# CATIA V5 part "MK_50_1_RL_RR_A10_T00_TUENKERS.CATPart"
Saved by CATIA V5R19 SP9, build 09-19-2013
Part number: MK_50_1_RL_RR_A10_T00_TUENKERS
Material "MISCHDICHTE": density 4834.5 kg/m3, Young's modulus 2e+11 Pa, Poisson ratio 0.266
Bounding box of the stored display mesh (mm): x -173.5 to 150.266, y -96.5 to 144, z -119.161 to 119.161
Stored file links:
  G:\Konstruktion\Modelle\Catia_V5\MK_50_1_RL_RR_A10_T00_TUENKERS.CATPart
  G:\Konstruktion\Modelle\Catia_V5\Spannarme\SPANNARM_KPL_50_A10_216884_TUENKERS.CATPart
  C:\Catia\Tuenkers_B19SP9HF86_64\win_b64\reffiles\standard\MetricThickPitch.txt
  G:\Konstruktion\Modelle\Catia_V5\MK2_50_1_A40_T00_TUENKERS.CATPart
  G:\Konstruktion\Modelle\Catia_V5\V2_50_1_BR3_ZL_ZR_RL_RR_A40_T12_TUENKERS.CATPart
  HANDHEBEL_KPL_50_63_TUENKERS.CATPart
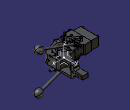
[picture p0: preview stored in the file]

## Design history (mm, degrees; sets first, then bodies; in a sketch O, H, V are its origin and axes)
AxisSystem1: origin (0, 0, 0), X (1, 0, 0), Y (0, 1, 0), Z (0, 0, 1)
Body1 (main body)
  Body2 "*DIT1\\*DIT8\\PartBody ( *SOL6 - wsp HANDHEBEL -  )"
    Solid1 "Solid.1": solid without history
  Assemble1: tool Body2
  Body3 "*DIT1\\*DIT9\\Body.9 ( *SOL4 - wsp T 12 ABFRAGE -  )"
    Sketch1 on face of Solid6, origin (0, 0, 88.5), H (1, 0, 0), V (0, 1, 0)
      line L1 (-98, 23.5) -> (-93.5, 23.5)
      line L2 (-93.5, 23.5) -> (-93.5, -23.5)
      line L3 (-93.5, -23.5) -> (-98, -23.5)
      line L4 (-98, -23.5) -> (-98, 23.5)
      line L5 (-126.5, 11.5) -> (-116.2, 11.5)
      line L6 (-116.2, 11.5) -> (-116.2, -5.5)
      line L7 (-116.2, -5.5) -> (-126.5, -5.5)
      line L8 (-126.5, -5.5) -> (-126.5, 11.5)
      reference projected line E1 (-126.5, -23.5) -> (-93.5, -23.5) from edge [face of Solid6 | face of Solid6]
      reference projected line E2 (-126.5, 23.5) -> (-93.5, 23.5) from edge [face of Solid6 | face of Solid6]
      reference projected line E3 (-93.5, 23.5) -> (-93.5, -23.5) from edge [face of Solid6 | face of Solid6]
      reference projected line E4 (-126.5, 23.5) -> (-93.5, 23.5) from edge [face of Solid6 | face of Solid6]
      reference projected line E5 (-126.5, 23.5) -> (-126.5, -23.5) from edge [face of Solid6 | face of Solid6]
      distance E1 L3 = 0
      distance L1 E2 = 0
      distance L2 L4 = 4.5
      distance L2 E3 = 0
      length L8 = 17
      distance L5 E4 = 12
      distance L6 L4 = 18.2
      distance L8 E5 = 0
      horizontal: L1 H, L3 H, L5 H, L7 H
      vertical: L2 V, L4 V, L6 V, L8 V
    Pad1: profile Sketch1, direction (0, 0, 1), length 8
    Chamfer1: length 4, angle 30, on edge [face of Pad1 from Sketch1.L2 | end face of Pad1]
    Chamfer2: length 8, angle 45, on edge [face of Pad1 from Sketch1.L8 | end face of Pad1]
  Assemble2: tool Body3
  Body4 "*DIT1\\*DIT10\\*DIT17\\PartBody ( *SOL17 - wsp DREHBOLZEN -  )"
    Solid2 "Solid.1": solid without history
  Assemble3: tool Body4
  Body5 "*DIT1\\*DIT10\\*DIT18\\PartBody ( *SOL18 - wsp STOESSEL -  )"
    Solid3 "Solid.1": solid without history
  Assemble4: tool Body5
  Body6 "*DIT1\\*DIT10\\MK_MK2_50_1_A10_A11_A12_T12_081112_3D_xSET3_1.1\\PartBody ( *SOL13 - wsp GEHAEUSE -  )"
    Solid4 "Solid.1": solid without history
  Assemble5: tool Body6
  Body7 "*DIT1\\MK_MK2_50_1_A10_A11_A12_T12_081112_3D_xSET2.1\\PartBody ( *SOL1 - wsp MK_MK2 50_1 -  -Non Smart-  )"
    Solid5 "Solid.1": solid without history
  Assemble6: tool Body7
  Body8 "*DIT1\\MK_MK2_50_1_A10_A11_A12_T12_081112_3D_xSET2.1\\Body.2 ( *SOL2 - wsp MK_MK2 50_1 -  -Non Smart-  )"
    Solid6 "Solid.1": solid without history
  Assemble7: tool Body8
  Body9 "*DIT1\\MK_MK2_50_1_A10_A11_A12_T12_081112_3D_xSET2.1\\Body.3 ( *SOL24 - wsp MK_MK2 50_1 -  )"
    Solid7 "Solid.1": solid without history
  Assemble8: tool Body9
  Body10 "*DIT1\\MK_MK2_50_1_A10_A11_A12_T12_081112_3D_xSET2.1\\Body.4 ( *SOL25 - wsp MK_MK2 50_1 -  )"
    Solid8 "Solid.1": solid without history
  Assemble9: tool Body10
  Body11 "*DIT1\\MK_MK2_50_1_A10_A11_A12_T12_081112_3D_xSET2.1\\Body.5 ( *SOL26 - wsp MK_MK2 50_1 -  )"
    Solid9 "Solid.1": solid without history
  Assemble10: tool Body11
  Body12 "*DIT1\\MK_MK2_50_1_A10_A11_A12_T12_081112_3D_xSET2.1\\Body.6 ( *SOL27 - wsp MK_MK2 50_1 -  )"
    Solid10 "Solid.1": solid without history
  Assemble11: tool Body12
  Body13 "*DIT1\\MK_MK2_50_1_A10_A11_A12_T12_081112_3D_xSET2.1\\Body.7 ( *SOL28 - wsp MK_MK2 50_1 -  )"
    Solid11 "Solid.1": solid without history
  Assemble12: tool Body13
  Rotate1: Axis edge [XY plane of AxisSystem1 | ZX plane of AxisSystem1], Angle 90, ToTransfor Assemble12
Body14 "Spannarm_kpl_50_A10_216884_Tuenkers", material "Steel"
  Sketch2 on xy-plane, origin (0, 0, 0), H (1, 0, 0), V (0, 1, 0)
    line L1 (43, 144) -> (15, 144)
    line L2 (35.6421, 1.701) -> (16.9706, -16.9706)
    line L3 (9.5, 9.5) -> (9.5, -9.5)
    line L4 (9.5, 9.5) -> (-9.5, 9.5)
    line L5 (-16.9706, 16.9706) -> (-9.5, 9.5)
    line L6 (10.6421, 44.5833) -> (-16.9706, 16.9706)
    line L7 (16.5, 58.7254) -> (16.5, 78.5)
    line L8 (43, 144) -> (43, 80)
    line L9 (9.5, -9.5) -> (16.9706, -16.9706)
    point P8 (43, 9.0589)
    point P9 (16.5, 51.7188)
    reference intersected line E1 through (0, 0) direction (-1, 0)
    reference intersected line E2 through (0, 0) direction (0, 1)
    reference intersected line E3 through (0, 0) direction (-0.7071, -0.7071)
    line L10 (41.5, 78.5) -> (41.5, 15.8431)
    reference intersected line E4 through (0, 0) direction (0, 1) from yz-plane
    line L11 (15, 80) -> (15, 144)
    point P10 (15, 80)
    reference intersected line E5 through (0, 0) direction (0, 1) from yz-plane
    arc A1 centre (43, 78.5) radius 1.5 from (41.5, 78.5) to (43, 80) cw
    arc A2 centre (15, 78.5) radius 1.5 from (16.5, 78.5) to (15, 80) ccw
    arc A3 centre (21.5, 15.8431) radius 20 from (35.6421, 1.701) to (41.5, 15.8431) ccw
    arc A4 centre (-3.5, 58.7254) radius 20 from (10.6421, 44.5833) to (16.5, 58.7254) ccw
    length L3 = 19
    length L4 = 19
    angle L5 L4 = 45
    angle L3 L9 = 45
    distance L2 L6 = 48
    distance L4 L1 = 134.5
    distance P9 L4 = 42.2188
    distance L4 E1 = 9.5
    distance L3 E2 = 9.5
    distance L2 E3 = 24
    distance L10 E4 = 41.5
    distance E5 L11 = 15
    distance L7 L10 = 25
    distance L8 L11 = 28
    length L8 = 64
    radius A3 = 20
    radius A4 = 20
    radius A1 = 1.5
    radius A2 = 1.5
    length L11 = 64
    vertical: L3 V
    horizontal: L4 H
    tangency: A3 L10, L2 A3, L7 A2, L10 A1, L7 A4, L6 A4
  Pad2: profile Sketch2, direction (0, 0, 1), length 34, mirrored extent
  Chamfer3: length 0.1, angle 45, on edge [start face of Pad2 | face of Pad2 from Sketch2.L3]; edge [start face of Pad2 | face of Pad2 from Sketch2.L4]; edge [face of Pad2 from Sketch2.L4 | end face of Pad2]; edge [face of Pad2 from Sketch2.L3 | end face of Pad2]
  Sketch3 on face of Pad2 from Sketch2.L8, origin (43, 0, 0), H (0, 1, 0), V (0, 0, 1)
    line L1 (144, -10) -> (144, 10)
    line L2 (103, 10) -> (144, 10)
    arc A1 centre (103, 18) radius 8 from (103, 10) to (95, 18) cw
    line L3 (95, 18) -> (95, 21.0383)
    line L4 (-18, 34) -> (75, 34)
    line L5 (-18, 34) -> (-18, 25)
    line L6 (74, 25) -> (-18, 25)
    arc A2 centre (74, 19) radius 6 from (74, 25) to (80, 19) cw
    line L7 (80, 19) -> (80, -19)
    arc A3 centre (74, -19) radius 6 from (80, -19) to (74, -25) cw
    line L8 (-18, -25) -> (74, -25)
    line L9 (-18, -25) -> (-18, -34)
    line L10 (75, -34) -> (-18, -34)
    line L11 (95, -21.0383) -> (95, -18)
    arc A4 centre (103, -18) radius 8 from (95, -18) to (103, -10) cw
    line L12 (103, -10) -> (144, -10)
    reference intersected line E1 through (0, 0) direction (-1, 0) from xy-plane
    reference intersected line E2 through (0, 0) direction (0, 1) from zx-plane
    reference intersected line E3 through (0, 0) direction (0, 1) from zx-plane
    reference intersected line E4 through (0, 0) direction (0, 1) from zx-plane
    line L13 (-23, -39) -> (149, -39)
    line L14 (149, -39) -> (149, 39)
    line L15 (149, 39) -> (-23, 39)
    line L16 (-23, 39) -> (-23, -39)
    reference intersected line E5 through (0, 0) direction (-1, 0) from xy-plane
    reference intersected line E6 through (0, 0) direction (0, 1) from zx-plane
    line L17 (75.5176, -33.9319) -> (87.5882, -30.6976)
    point P18 (95, -24)
    arc A5 centre (85, -21.0383) radius 10 from (95, -21.0383) to (87.5882, -30.6976) cw
    arc A6 centre (75, -32) radius 2 from (75, -34) to (75.5176, -33.9319) ccw
    point P23 (75, -34)
    line L18 (87.5882, 30.6976) -> (75.5176, 33.9319)
    arc A7 centre (75, 32) radius 2 from (75, 34) to (75.5176, 33.9319) cw
    point P26 (75, 34)
    arc A8 centre (85, 21.0383) radius 10 from (87.5882, 30.6976) to (95, 21.0383) cw
    distance L12 E1 = 10
    distance L12 L2 = 20
    distance L4 L10 = 68
    distance L6 L8 = 50
    distance L10 L12 = 24
    distance L8 L10 = 9
    radius A2 = 6
    radius A3 = 6
    radius A1 = 8
    radius A4 = 8
    distance L7 E2 = 80
    distance L3 E3 = 95
    distance L1 L5 = 162
    distance E4 L1 = 144
    distance L16 L14 = 172
    distance L15 L13 = 78
    distance L13 E5 = 39
    distance L14 E6 = 149
    radius A5 = 10
    angle L10 L17 = 15
    radius A6 = 2
    distance L11 P23 = 20
    angle L4 L18 = 15
    distance P26 L3 = 20
    radius A8 = 10
    radius A7 = 2
    tangency: L6 A2, A2 L7, L7 A3, A3 L8, L3 A1, A1 L2, A4 L12, A4 L11, A5 L11, A5 L17, A6 L10, A6 L17, A7 L4, A7 L18, A8 L18, A8 L3
    vertical: L1 V, L14 V, L16 V
    horizontal: L12 H, L13 H, L15 H
    coincidence: L5 L9, L11 L3, L11 P18
  Pocket1: profile Sketch3, direction (-1, 0, 0), length 91
  Sketch4 on face of Pad2 from Sketch2.L8, origin (43, 131.0889, -0.3784), H (0, 1, 0), V (0, 0, 1)
    point P1 (3.9111, 0.3784)
    reference intersected line E1 through (0, 0.3784) direction (-1, 0) from xy-plane
    reference intersected line E2 through (-131.0889, 0) direction (0, 1) from zx-plane
    distance P1 E2 = 135
    coincidence: P1 E1
  Hole1: placed by Sketch4, at (43, 135, 0) direction (-1, 0, 0), diameter 6, through (limit type 6)
  Sketch5 on face of Pad2 from Sketch2.L8, origin (43, 113.9529, 0.5693), H (0, 1, 0), V (0, 0, 1)
    point P1 (-8.9529, -0.5693)
    reference projected point E1 (21.0471, -0.5693) from axis of face of Hole1
    reference intersected line E2 through (0, -0.5693) direction (-1, 0) from xy-plane
    distance P1 E1 = 30
    coincidence: P1 E2
  Hole2: placed by Sketch5, at (43, 105, 0) direction (-1, 0, 0), diameter 6, through (limit type 6)
  Sketch6 on face of Pad2 from Sketch2.L8, origin (43, 123.4122, -0.1089), H (0, 1, 0), V (0, 0, 1)
    point P1 (-3.4122, 0.1089)
    reference projected point E1 (11.5878, 0.1089) from axis of face of Hole1
    reference projected point E2 (-18.4122, 0.1089) from axis of face of Hole2
    distance P1 E1 = 15
    distance E2 P1 = 15
  Hole3: placed by Sketch6, at (43, 120, 0) direction (-1, 0, 0), diameter 9, through (limit type 6)
  Sketch7 on face of Pad2 from Sketch2.L8, origin (43, 93.5248, 1.4062), H (0, 1, 0), V (0, 0, 1)
    point P1 (-3.5248, -1.4062)
    reference projected point E1 (26.4752, -1.4062) from axis of face of Hole3
    reference projected point E2 (11.4752, -1.4062) from axis of face of Hole2
    distance P1 E1 = 30
    distance P1 E2 = 15
  Hole4: placed by Sketch7, at (43, 90, 0) direction (-1, 0, 0), diameter 9, through (limit type 6)
  Sketch8 on face of Pad2 from Sketch2.L9, origin (13.7879, -13.7879, 28.7565), H (0.7071, -0.7071, 0), V (0, 0, 1)
    point P1 (-1.4991, 0.2435)
    reference intersected line E1 through (0, -28.7565) direction (-1, 0) from xy-plane
    reference projected line E2 (-19.4991, -62.7565) -> (-19.4991, 5.2435) from edge [face of Pad2 from Sketch2.L3 | face of Pad2 from Sketch2.L4]
    distance P1 E1 = 29
    distance E2 P1 = 18
  Hole5: placed by Sketch8, at (12.7279, -12.7279, 29) direction (0.7071, 0.7071, 0), diameter 4.917, depth 16, V-bottom angle 120, threaded "M6", thread diameter 6, thread depth 14, pitch 1
  RectPattern1: of Hole5, direction 1 instances 2, spacing 58, along edge [face of Pad2 from Sketch2.L3 | face of Pad2 from Sketch2.L4] reversed, direction 2 instances 2, spacing 36, along edge [face of Pad2 from Sketch2.L9 | face of Pocket1] reversed
  Body15 "KLEMMFLANSCH KPL"
    Sketch9 on xy-plane, origin (0, 0, 0), H (1, 0, 0), V (0, 1, 0)
      line L1 (-18.3848, 15.5563) -> (-26.8771, 7.064)
      line L2 (-26.8771, 7.064) -> (-18.7454, -1.0677)
      line L3 (-18.7454, -1.0677) -> (-23.6951, -6.0175)
      line L4 (-23.6951, -6.0175) -> (-6.0175, -23.6951)
      line L5 (-6.0175, -23.6951) -> (-1.0677, -18.7454)
      line L6 (-1.0677, -18.7454) -> (7.064, -26.8771)
      line L7 (7.064, -26.8771) -> (16.9635, -16.9776)
      line L8 (16.9635, -16.9776) -> (9.3267, -9.3409)
      line L9 (9.3267, -9.3409) -> (-9.3409, -9.3409)
      point P10 (-9.3409, -9.3409)
      line L10 (-9.3409, -9.3409) -> (-9.3409, 6.5125)
      line L11 (-9.3409, 6.5125) -> (-18.3848, 15.5563)
      reference intersected line E1 through (0, 0) direction (-0.7071, -0.7071)
      reference intersected line E2 through (0, 0) direction (-0.7071, 0.7071)
      distance L4 L8 = 21
      angle L5 L6 = 90
      angle L9 L8 = 45
      distance L7 L5 = 11.5
      distance L5 L3 = 25
      distance L7 L1 = 48
      distance P10 L8 = 13.2
      distance P10 L5 = 12.5
      distance L4 L6 = 7
      angle L9 L10 = 90
      distance E2 L11 = 2
      distance L11 L8 = 1.99
      coincidence: L2 L6, E1 P10
    Pad3: profile Sketch9, direction (0, 0, 1), length 34, opposite side length -24
    Sketch10 on face of Pad3 from Sketch9.L6, origin (-9.9066, -9.9066, 0), H (0.7071, -0.7071, 0), V (0, 0, 1)
      circle A1 centre (18, 29) radius 5
      point P1 (18, 29)
      point P2 (18, 29)
      reference projected line E1 (12.5, 34) -> (24, 34) from edge [face of Pad3 from Sketch9.L6 | end face of Pad3]
      reference projected line E2 (24, 24) -> (24, 34) from edge [face of Pad3 from Sketch9.L7 | face of Pad3 from Sketch9.L6]
      radius A1 = 5
      distance E1 P2 = 5
      distance P2 E2 = 6
      coincidence: P2 P1
    Pad4: profile Sketch10, direction (-0.7071, -0.7071, 0), length 1.2
    RectPattern2: of Pad4, direction 1 instances 2, spacing 36, along edge [start face of Pad3 | face of Pad3 from Sketch9.L4] reversed
    Chamfer4: length 0.1, angle 45, on edge [face of Pad4 from Sketch10.A1 | end face of Pad4]; edge [face of RectPattern2 | face of RectPattern2]
    Sketch11 on face of Pad3 from Sketch9.L6, origin (-9.9066, -9.9066, 0), H (0.7071, -0.7071, 0), V (0, 0, 1)
      circle A1 centre (18, 29) radius 3
      point P1 (18, 29)
      reference projected line E1 (12.5, 24) -> (24, 24) from edge [start face of Pad3 | face of Pad3 from Sketch9.L6]
      reference projected line E2 (24, 24) -> (24, 34) from edge [face of Pad3 from Sketch9.L7 | face of Pad3 from Sketch9.L6]
      radius A1 = 3
      distance P1 E1 = 5
      distance E2 P1 = 6
    Pad5: profile Sketch11, direction (0.7071, 0.7071, 0), length 20
    RectPattern3: of Pad5, direction 1 instances 2, spacing 36, along edge [start face of Pad3 | face of Pad3 from Sketch9.L4] reversed
    Sketch12 on end face of Pad4, origin (-10.7551, -10.7551, 0), H (0.7071, -0.7071, 0), V (0, 0, 1)
      circle A1 centre (18, 29) radius 5
      point P1 (18, 29)
      circle A2 centre (-18, 29) radius 5
      point P2 (-18, 29)
      reference projected line E1 (-24, 24) -> (-12.5, 24) from edge [start face of Pad3 | face of Pad3 from Sketch9.L2]
      reference projected line E2 (12.5, 24) -> (24, 24) from edge [start face of Pad3 | face of Pad3 from Sketch9.L6]
      reference projected line E3 (24, 24) -> (24, 34) from edge [face of Pad3 from Sketch9.L7 | face of Pad3 from Sketch9.L6]
      reference projected line E4 (-24, 24) -> (-24, 34) from edge [face of Pad3 from Sketch9.L2 | face of Pad3 from Sketch9.L1]
      radius A1 = 5
      radius A2 = 5
      distance E1 P2 = 5
      distance E2 P1 = 5
      distance E3 P1 = 6
      distance E4 P2 = 6
    Pad6: profile Sketch12, direction (-0.7071, -0.7071, 0), length 6
    Fillet1: radius 0.5, on edge [face of Pad6 from Sketch12.A1 | end face of Pad6]; edge [face of Pad6 from Sketch12.A2 | end face of Pad6]
    Chamfer5: length 0.1, angle 45, on edge [face of Pad3 from Sketch9.L9 | end face of Pad3]; edge [face of Pad3 from Sketch9.L10 | end face of Pad3]
    Mirror1: of the body so far, about xy-plane
  Assemble13: tool Body15
  Sketch13 on face of Pocket1 from Sketch3.L6, origin (0, 0, 25), H (1, 0, 0), V (0, -1, 0)
    line L1 (16.9706, 16.9706) -> (9.5, 9.5)
    line L2 (9.5, 9.5) -> (9.5, -9.5)
    point P3 (9.5, -9.5)
    line L3 (9.5, -9.5) -> (-9.5, -9.5)
    line L4 (-9.5, -9.5) -> (-16.9706, -16.9706)
    line L5 (-16.9706, -16.9706) -> (0.7071, -34.6482)
    line L6 (0.7071, -34.6482) -> (34.6482, -0.7071)
    line L7 (34.6482, -0.7071) -> (16.9706, 16.9706)
    reference intersected line E1 through (0, 0) direction (0.7071, 0.7071)
    reference intersected line E2 through (0, 0) direction (0.7071, -0.7071)
    reference intersected line E3 through (0, 0) direction (0.7071, -0.7071)
    distance L1 L6 = 25
    angle L2 L3 = 90
    length L2 = 19
    length L3 = 19
    distance L7 L5 = 48
    distance L7 E3 = 24
    coincidence: E1 L1, L1 L4, E2 P3
  Pad7: profile Sketch13, direction (0, 0, -1), length 1
  Mirror2: of Pad7, Sketch13, about xy-plane
Body16 "ENDLAGENRASTE_LINKS"
  Body17 "LUMP108"
    Solid12 "Manifold Solid #2147": solid without history
  Assemble14: tool Body17
  Body18 "LUMP109"
    Solid13 "Manifold Solid #2556": solid without history
  Assemble15: tool Body18
  Body19 "LUMP110"
    Solid14 "Manifold Solid #2941": solid without history
  Assemble16: tool Body19
  Body20 "LUMP111"
    Solid15 "Manifold Solid #3571": solid without history
  Assemble17: tool Body20
  Body21 "LUMP112"
    Solid16 "Manifold Solid #4879": solid without history
  Assemble18: tool Body21
  Body22 "LUMP114"
    Solid17 "Manifold Solid #6444": solid without history
  Assemble19: tool Body22
  Body23 "LUMP117"
    Solid18 "Manifold Solid #8121": solid without history
  Assemble20: tool Body23
  Body24 "LUMP118"
    Solid19 "Manifold Solid #9264": solid without history
  Assemble21: tool Body24
  Body25 "LUMP120"
    Solid20 "Manifold Solid #10792": solid without history
  Assemble22: tool Body25
  Body26 "LUMP122"
    Solid21 "Manifold Solid #11586": solid without history
  Assemble23: tool Body26
  Body27 "LUMP126"
    Solid22 "Manifold Solid #12918": solid without history
  Assemble24: tool Body27
  Body28 "LUMP127"
    Solid23 "Manifold Solid #13327": solid without history
  Assemble25: tool Body28
  Body29 "LUMP130"
    Solid24 "Manifold Solid #14250": solid without history
  Assemble26: tool Body29
  Body30 "LUMP132"
    Solid25 "Manifold Solid #15068": solid without history
  Assemble27: tool Body30
  Body31 "LUMP133"
    Solid26 "Manifold Solid #15325": solid without history
  Assemble28: tool Body31
  Body32 "LUMP134"
    Solid27 "Manifold Solid #15582": solid without history
  Assemble29: tool Body32
  Body33 "LUMP135"
    Solid28 "Manifold Solid #15839": solid without history
  Assemble30: tool Body33
  Body34 "LUMP124"
    Solid29 "Manifold Solid #12404": solid without history
  Assemble31: tool Body34
  Rotate2: Axis edge, Angle 90, ToTransfor Assemble31
Body35 "ENDLAGENRASTE_RECHTS"
  Solid30 "Manifold Solid #290": solid without history
  Body36 "LUMP105"
    Solid31 "Manifold Solid #920": solid without history
  Assemble32: tool Body36
  Body37 "LUMP106"
    Solid32 "Manifold Solid #1329": solid without history
  Assemble33: tool Body37
  Body38 "LUMP107"
    Solid33 "Manifold Solid #1738": solid without history
  Assemble34: tool Body38
  Body39 "LUMP113"
    Solid34 "Manifold Solid #6187": solid without history
  Assemble35: tool Body39
  Body40 "LUMP115"
    Solid35 "Manifold Solid #6701": solid without history
  Assemble36: tool Body40
  Body41 "LUMP116"
    Solid36 "Manifold Solid #7411": solid without history
  Assemble37: tool Body41
  Body42 "LUMP119"
    Solid37 "Manifold Solid #10407": solid without history
  Assemble38: tool Body42
  Body43 "LUMP121"
    Solid38 "Manifold Solid #11177": solid without history
  Assemble39: tool Body43
  Body44 "LUMP123"
    Solid39 "Manifold Solid #11995": solid without history
  Assemble40: tool Body44
  Body45 "LUMP124"
    Solid40 "Manifold Solid #12404": solid without history
    Symmetry1: Reference ZX plane of AxisSystem1, ToTransfor Solid40
  Assemble41: tool Body45
  Body46 "LUMP125"
    Solid41 "Manifold Solid #12661": solid without history
  Assemble42: tool Body46
  Body47 "LUMP128"
    Solid42 "Manifold Solid #13736": solid without history
  Assemble43: tool Body47
  Body48 "LUMP129"
    Solid43 "Manifold Solid #13993": solid without history
  Assemble44: tool Body48
  Body49 "LUMP131"
    Solid44 "Manifold Solid #14659": solid without history
  Assemble45: tool Body49
  Body50 "LUMP136"
    Solid45 "Manifold Solid #16096": solid without history
  Assemble46: tool Body50
  Rotate3: Axis edge, Angle 90, ToTransfor Assemble46
Body51 "Handhebel_KPL_218625_TUENKERS.1"
  Solid46: solid without history
  Body52 "Handhebel_KPL_218625_TUENKERS.2"
    Solid47: solid without history
  Assemble47: tool Body52
  Translate1: Direction edge [ZX plane of AxisSystem1 | YZ plane of AxisSystem1], ToTransfor Assemble47, Length 25
  Translate2: Direction edge [XY plane of AxisSystem1 | ZX plane of AxisSystem1], ToTransfor Translate1, Length -68
  Translate3: Direction edge [YZ plane of AxisSystem1 | XY plane of AxisSystem1], ToTransfor Translate2, Length -4
Body53 "Handhebel_KPL_218625_TUENKERS.1"
  Solid48: solid without history
  Body54 "Handhebel_KPL_218625_TUENKERS.2"
    Solid49: solid without history
  Assemble48: tool Body54
  Translate4: Direction edge [ZX plane of AxisSystem1 | YZ plane of AxisSystem1], Length 25, ToTransfor Assemble48
  Translate5: Direction edge [XY plane of AxisSystem1 | ZX plane of AxisSystem1], Length -68, ToTransfor Translate4
  Translate6: Direction edge [YZ plane of AxisSystem1 | XY plane of AxisSystem1], Length -4, ToTransfor Translate5
  Symmetry2: ToTransfor Translate6, Reference XY plane of AxisSystem1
